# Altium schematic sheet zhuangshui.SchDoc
size A4
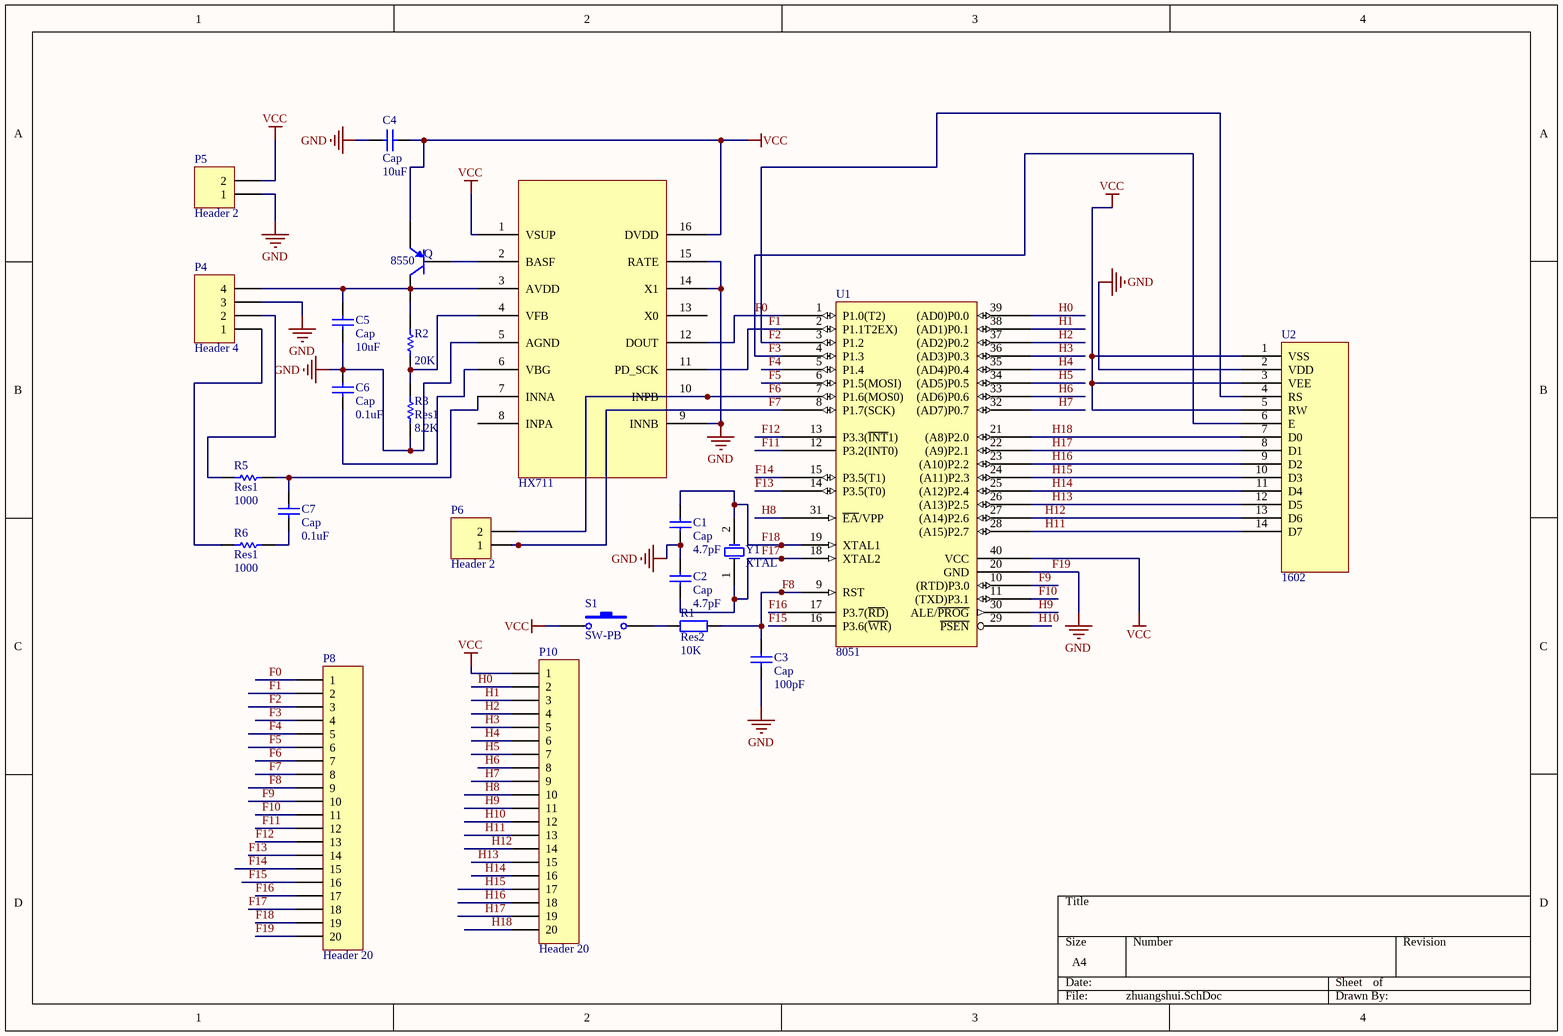
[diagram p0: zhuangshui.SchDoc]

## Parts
?  HX711  [SOP16 - duplicate]
C1  Cap  value 4.7pF  [RAD-0.3]
C2  Cap  value 4.7pF  [RAD-0.3]
C3  Cap  value 100pF  [RAD-0.3]
C4  Cap  value 10uF  [RAD-0.3]
C5  Cap  value 10uF  [RAD-0.3]
C6  Cap  value 0.1uF  [RAD-0.3]
C7  Cap  value 0.1uF  [RAD-0.3]
P4  Header 4  [HDR1X4]
P5  Header 2  [HDR1X2]
P6  Header 2  [HDR1X2]
P8  Header 20  [HDR1X20]
P10  Header 20  [HDR1X20]
Q  8550  [TO-92A]
R1  Res2  value 10K  [AXIAL-0.4]
R2  value 20K  [AXIAL-0.3]
R3  Res1  value 8.2K  [AXIAL-0.3]
R5  Res1  value 1000  [AXIAL-0.3]
R6  Res1  value 1000  [AXIAL-0.3]
S1  SW-PB  [SPST-2]
U1  8051  [SOT129-1]
U2  1602  [1602]
Y1  XTAL  [R38]

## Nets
F19: ?.5(AGND) ?.9(INNB) ?.14(X1) ?.15(RATE) C1.1 C2.2 C3.1 C4.1 C5.1 C6.2 P4.3 P5.1 P8.20 R3.1 U1.20(GND) U2.2(VDD)  [also labelled GND]
VCC: ?.1(VSUP) ?.16(DVDD) C4.2 P5.2 P10.1 Q.1(E) S1.1 U1.40(VCC) U2.1(VSS) U2.3(VEE) U2.5(RW)
F0: ?.12(DOUT) P8.1 P8.4 U1.1(P1.0(T2)) U1.4(P1.3) U2.6(E)  [also labelled F3]
F1: ?.11(PD_SCK) P8.2 U1.2(P1.1T2EX))
F2: P8.3 U1.3(P1.2) U2.4(RS)
F4: P8.5 U1.5(P1.4)
F5: P8.6 U1.6(P1.5(MOSI))
F6: ?.10(INPB) P6.2 P8.7 U1.7(P1.6(MOS0))
F7: P6.1 P8.8 U1.8(P1.7(SCK))
F8: C3.2 P8.9 R1.2 U1.9(RST)
F9: P8.10 U1.10((RTD)P3.0)
F10: P8.11 U1.11((TXD)P3.1)
F11: P8.12 U1.12(P3.2(INT0))
F12: P8.13 U1.13(P3.3(~{INT}1))
F13: P8.14 U1.14(P3.5(T0))
F14: P8.15 U1.15(P3.5(T1))
F15: P8.16 U1.16(P3.6(~{WR}))
F16: P8.17 U1.17(P3.7(~{RD}))
F17: C2.1 P8.18 U1.18(XTAL2) Y1.1(OSC1)
F18: C1.2 P8.19 U1.19(XTAL1) Y1.2(OSC2)
H0: P10.2 U1.39((AD0)P0.0)
H1: P10.3 U1.38((AD1)P0.1)
H2: P10.4 U1.37((AD2)P0.2)
H3: P10.5 U1.36((AD3)P0.3)
H4: P10.6 U1.35((AD4)P0.4)
H5: P10.7 U1.34((AD5)P0.5)
H6: P10.8 U1.33((AD6)P0.6)
H7: P10.9 U1.32((AD7)P0.7)
H8: P10.10 U1.31(~{EA}/VPP)
H9: P10.11 U1.30(ALE/~{PROG})
H10: P10.12 U1.29(~{PSEN})
H11: P10.13 U1.28((A15)P2.7) U2.14(D7)
H12: P10.14 U1.27((A14)P2.6) U2.13(D6)
H13: P10.15 U1.26((A13)P2.5) U2.12(D5)
H14: P10.16 U1.25((A12)P2.4) U2.11(D4)
H15: P10.17 U1.24((A11)P2.3) U2.10(D3)
H16: P10.18 U1.23((A10)P2.2) U2.9(D2)
H17: P10.19 U1.22((A9)P2.1) U2.8(D1)
H18: P10.20 U1.21((A8)P2.0) U2.7(D0)
Net?_2: ?.2(BASF) Q.2(B)
Net?_3: ?.3(AVDD) C5.2 P4.4
Net?_4: ?.4(VFB) R2.1 R3.2
Net?_6: ?.6(VBG) C6.1
Net?_7: ?.7(INNA) C7.2 R5.2
NetC7_1: C7.1 R6.2
NetP4_1: P4.1 R6.1
NetP4_2: P4.2 R5.1
NetQ_3: Q.3(C) R2.2
NetR1_1: R1.1 S1.2

Not connected (* = marked no-connect by the designer): ? 8(INPA) 13(X0)

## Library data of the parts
C1-C7 = Cap: Capacitor
P4 = Header 4: Header, 4-Pin
P5 P6 = Header 2: Header, 2-Pin
P8 P10 = Header 20: Header, 20-Pin
Q = 2N3906: PNP General Purpose Amplifier
R1 = Res2: Resistor
R2 R3 R5 R6 = Res1: Resistor
S1 = SW-PB: Switch
U1 = AT89S52
Y1 = XTAL: Crystal Oscillator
